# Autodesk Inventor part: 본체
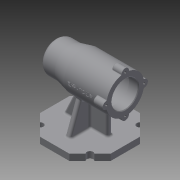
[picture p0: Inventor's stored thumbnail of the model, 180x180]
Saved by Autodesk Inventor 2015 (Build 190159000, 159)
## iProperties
Created: 2019-12
Part Number: 본체
Material: 일반
Document SubType Name: Modeling
Designer: 101548
Density: 1 g/cm^3
Appearance: 기본값
Mass: 268.817 g
Surface Area: 714.68 cm^2
Volume: 268.817 cm^3
Author: 101548
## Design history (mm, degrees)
sketch "스케치1" dims "d0" = 112
  geometry: L1 (23.196, 56)-(56, 23.196); L2 (56, 23.196)-(56, -23.196); L3 (56, -23.196)-(23.196, -56); L4 (23.196, -56)-(-23.196, -56); L5 (-23.196, -56)-(-56, -23.196); L6 (-56, -23.196)-(-56, 23.196); L7 (-56, 23.196)-(-23.196, 56); L8 (-23.196, 56)-(23.196, 56); 4 further points
  constraints: 16 end point, 2 coincident, 1 midpoint, 1 vertical alignment, 19 other
extrude "돌출1" new body sketch "스케치1" distance "d1" = 10; taper "d2" = 0 deg
sketch "스케치2"
  geometry: L1 (-56, -23.196)-(-23.196, -56) reference; C1 r 5 at (-39.598, -39.598); 1 further point
  constraints: 1 centre point, 1 midpoint
  dimensions: "d3" = 10 diameter of C1
extrude "돌출2" cut sketch "스케치2" stored distance "d4" = 10; taper "d5" = 0 deg
sketch "스케치3"
  geometry: L1 (-56, 23.196)-(-23.196, 56) reference; L2 (23.196, 56)-(56, 23.196) reference; L3 (56, -23.196)-(23.196, -56) reference; C1 r 5 at (-39.598, 39.598); C2 r 5 at (39.598, 39.598); C3 r 5 at (39.598, -39.598); 1 further point
  constraints: 3 centre point, 3 midpoint
  dimensions: "d6" = 10 diameter of C1; "d7" = 10 diameter of C2; "d8" = 10 diameter of C3
extrude "돌출3" cut sketch "스케치3" stored distance "d9" = 10; taper "d10" = 0 deg
sketch "스케치4"
  geometry: L1 (56, -23.196)-(56, 23.196) reference; L2 (23.196, 56)-(-23.196, 56) reference; L3 (-56, 23.196)-(-56, -23.196) reference; L4 (-23.196, -56)-(23.196, -56) reference; L5 (-38, -4)-(31, -4); L6 (31, -4)-(31, 4); L7 (31, 4)-(-38, 4); L8 (-38, 4)-(-38, -4); L9 (-4, -36)-(4, -36); L10 (4, -36)-(4, 36); L11 (4, 36)-(-4, 36); L12 (-4, 36)-(-4, -36); 1 further point
  constraints: 16 end point, 4 parallel, 2 horizontal, 2 perpendicular
  dimensions: "d11" = 4 distance from line of L7 point (0, 0); "d12" = 8 distance of L5.end L6.end; "d13" = 4 distance from line of L10 point (0, 0); "d14" = 8 distance of L9.start L9.end; "d15" = 25 distance between parallel lines of L1 L6; "d16" = 18 distance between parallel lines of L3 L8; "d17" = 20 distance between parallel lines of L4 L9; "d18" = 20 distance between parallel lines of L2 L11
extrude "돌출4" join sketch "스케치4" distance "d19" = 70; taper "d20" = 0 deg
feature "면 기울기1" dims angle "d21" = 20 deg
feature "면 기울기2" dims angle "d22" = 25 deg
sketch "스케치5"
  geometry: L1 (56, 0)-(-56, 0) reference; L2 (-56, 0)-(-56, 10) reference; L3 (-56, 10)-(-31, 10) reference; L4 (-31, 10)-(-31, 80) reference; L5 (-31, 80)-(5.358, 80) reference; L6 (5.358, 80)-(38, 10) reference; L7 (38, 10)-(56, 10) reference; L8 (56, 10)-(56, 0) reference; L9 (56, 80)-(-56, 80); L10 (-56, 80)-(-56, 110); L11 (-56, 110)-(11, 110); L12 (11, 110)-(31, 105); L13 (31, 105)-(56, 105); L14 (56, 105)-(56, 80); 3 further points
  constraints: 12 end point, 3 perpendicular, 2 midpoint, 1 collinear, 1 horizontal, 1 parallel, 1 vertical alignment
  dimensions: "d23" = 30 distance of L9.end L10.end; "d24" = 25 distance of L13.end L9.start; "d25" = 112 distance of L9.start L9.end; "d26" = 25 distance of L12.end L13.end; "d27" = 45 horizontal distance of L11.end L13.end
revolve "회전1" sketch "스케치5" stored, may be unused: angle "d28" = 90 deg
sketch "스케치6"
  geometry: C1 r 6 at (-30, 0); 2 further points
  constraints: 1 centre point, 1 horizontal alignment, 1 other
  dimensions: "d29" = 12 diameter of C1
extrude "돌출5" join sketch "스케치6" distance "d30" = 16; taper "d31" = 0 deg
fillet "모깎기1" dims "d32" = 3
fillet "모깎기2" dims "d33" = 1
sketch "스케치7"
  geometry: C1 r 21 at (30, 0); A1 r 30 centre (30, 0) between (36.771, -29.226) and (59.226, -6.771) reference; 1 further point
  constraints: 1 centre point, 1 coincident
  dimensions: "d37" = 42 diameter of C1
extrude "돌출6" cut sketch "스케치7" distance "d38" = 15; taper "d39" = 0 deg
sketch "스케치8"
  geometry: C1 r 21 at (0, 0) reference; C2 r 24 at (0, 0); 1 further point
  constraints: 1 centre point, 1 coincident
  dimensions: "d40" = 48 diameter of C2
extrude "돌출7" cut sketch "스케치8" distance "d41" = 54; taper "d42" = 0 deg
sketch "스케치9"
  geometry: C1 r 24 at (0, 0) reference; C2 r 21 at (0, 0); 1 further point
  constraints: 1 centre point, 1 coincident
  dimensions: "d43" = 42 diameter of C2
extrude "돌출8" cut sketch "스케치9" distance "d44" = 12; taper "d45" = 0 deg
sketch "스케치10"
  geometry: C1 r 21 at (0, 0) reference; C2 r 17.5 at (0, 0); 1 further point
  constraints: 1 centre point, 1 coincident
  dimensions: "d46" = 35 diameter of C2
extrude "돌출9" cut sketch "스케치10" distance "d47" = 18; taper "d48" = 0 deg
sketch "스케치11"
  geometry: C1 r 17.5 at (0, 0) reference; C2 r 16 at (0, 0); 1 further point
  constraints: 1 centre point, 1 coincident
  dimensions: "d49" = 32 diameter of C2
extrude "돌출10" cut sketch "스케치11" distance "d50" = 4; taper "d51" = 0 deg
sketch "스케치12"
  geometry: C1 r 16 at (0, 0) reference; C2 r 10.5 at (0, 0); 1 further point
  constraints: 1 centre point, 1 coincident
  dimensions: "d52" = 21 diameter of C2
extrude "돌출11" cut sketch "스케치12" distance "d53" = 3; taper "d54" = 0 deg
fillet "모깎기3" dims "d55" = 3
fillet "모깎기4" dims "d56" = 0.3
fillet "모깎기5" dims "d57" = 3
chamfer "모따기1" distance "d58" = 1; stored, may be unused: second distance "d59" = 2, angle "d60" = 45 deg
sketch "스케치13"
  geometry: A1 r 6 centre (0, 0) between (-0.171, 5.998) and (-0.171, -5.998) reference; 1 further point
hole "구멍1" sketch "스케치13" at (0, 0) diameter "d61" = 3.242; stored, may be unused: countersink angle "d65" = 90 deg, drill point angle "d67" = 118 deg; dims "d62" = 8, "d63" = 4, "d64" = 2, "d66" = 11
fillet "모깎기6" dims "d71" = 10
fillet "모깎기7" dims "d72" = 3
fillet "모깎기8" dims "d73" = 3
fillet "모깎기9" dims "d74" = 3
fillet "모깎기10" dims "d75" = 3
node "작업 평면1"
sketch "스케치14"
  geometry: L1 (33.5, 36)-(33.5, 30.171) reference; L2 (33.5, 5.998)-(33.5, -5.998) reference; 3 further points
  constraints: 1 horizontal alignment, 1 midpoint, 1 other
  dimensions: "d76" = 41 distance from line of L1 point (-7.5, 0)
feature "엠보싱1" sketch "스케치14" dims "d77" = 0.5, "d78" = 0
node "솔리드1"
pattern_circular "원형 패턴1" dims "d35" = 360 deg
pattern_circular "원형 패턴2" dims angle "d69" = 360 deg
node "절단 모서리 투영1"
